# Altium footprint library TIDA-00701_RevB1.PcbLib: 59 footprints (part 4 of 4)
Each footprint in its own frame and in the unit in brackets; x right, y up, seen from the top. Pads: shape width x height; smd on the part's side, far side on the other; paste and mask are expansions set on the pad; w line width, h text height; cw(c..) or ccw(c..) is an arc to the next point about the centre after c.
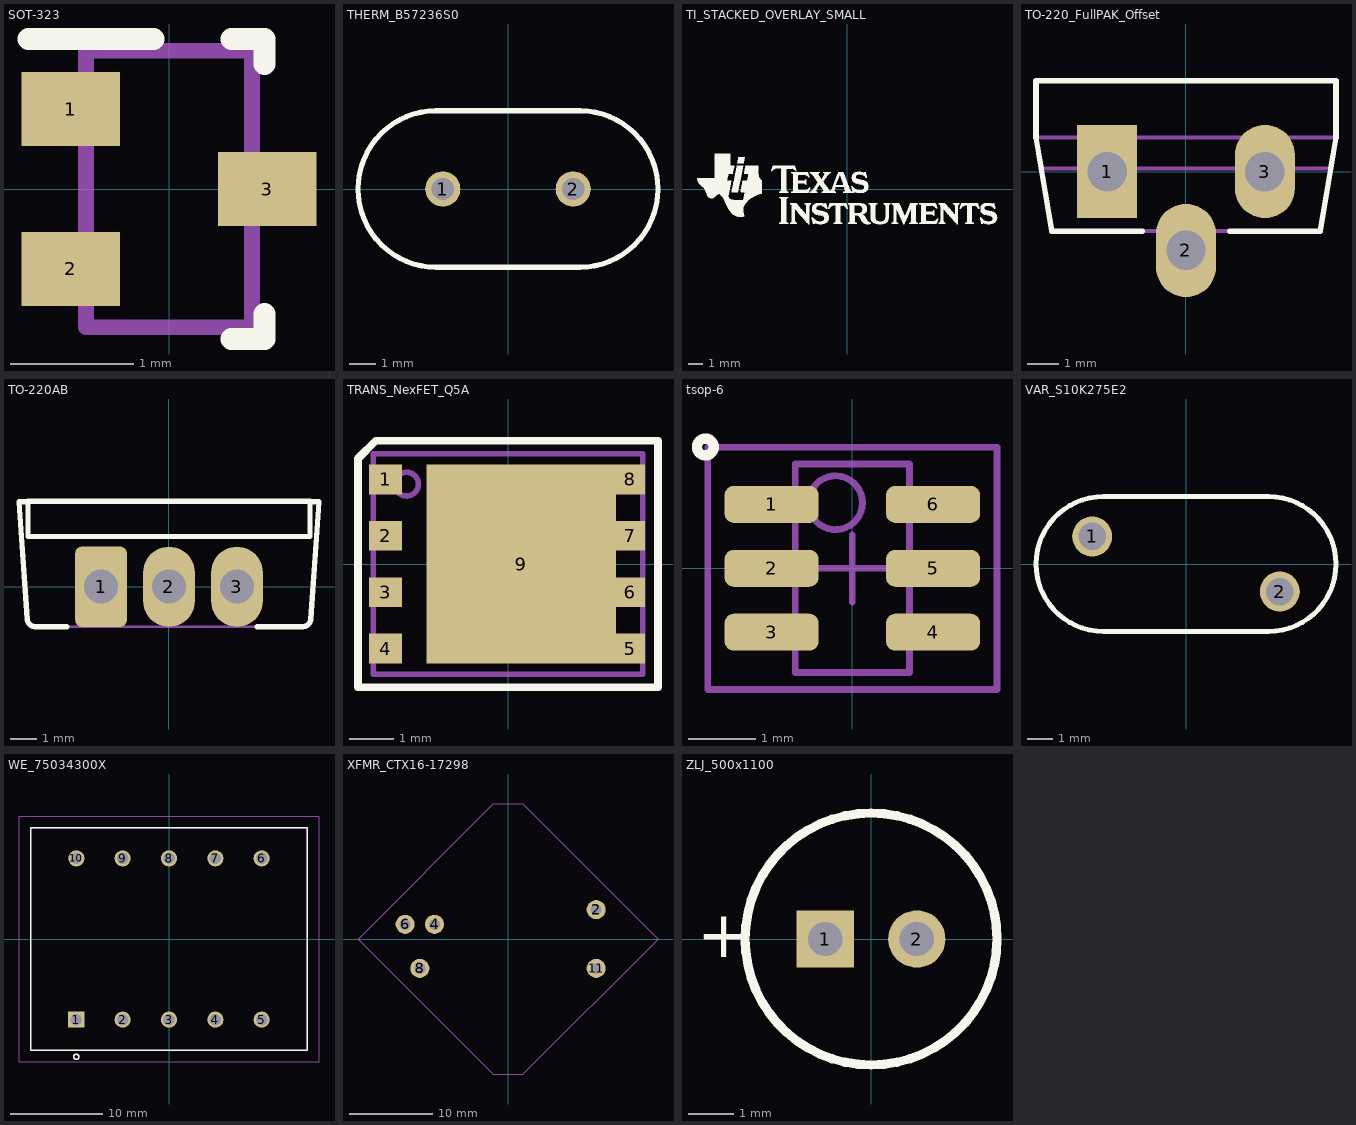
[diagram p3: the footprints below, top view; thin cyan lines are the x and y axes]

## SOT-323 [mm] "Zetex recommended land pattern.  March 2007"
height 1.1
pads (3):
  rect 0.8x0.6 smd: 1(-0.8,0.65) 2(-0.8,-0.65) 3(0.8,0)
Top Overlay:
  lines w0.178: -1.143,1.219 -0.127,1.219 ; 0.508,-1.219 0.775,-1.219 0.775,-1.016 ; 0.508,1.219 0.775,1.219 0.775,1.016
Mechanical 5:
  lines w0.127: -1.125,-0.8 -1.125,-0.5 -0.975,-0.5 -0.935,-0.5 -0.884,-0.5 -0.725,-0.5 -0.675,-0.5 -0.675,-0.8 -0.725,-0.8 -0.884,-0.8 -0.935,-0.8 -0.975,-0.8 -1.125,-0.8 ; -1.125,0.5 -1.125,0.8 -0.975,0.8 -0.935,0.8 -0.884,0.8 -0.725,0.8 -0.675,0.8 -0.675,0.5 -0.725,0.5 -0.884,0.5 -0.935,0.5 -0.975,0.5 -1.125,0.5 ; -0.675,-1.125 -0.675,1.125 0.675,1.125 0.675,-1.125 -0.675,-1.125 ; 0.675,-0.15 0.725,-0.15 0.884,-0.15 0.935,-0.15 0.975,-0.15 1.125,-0.15 1.125,0.15 0.975,0.15 0.935,0.15 0.884,0.15 0.725,0.15 0.675,0.15 0.675,-0.15
  text ".Designator" at 0.434,-0.617 h0.89
3D body: height 1.13, standoff 0.02, extent -1.125,-1.125 1.125,1.125

## THERM_B57236S0 [mm] "EPCOS"
height 16
pads (2):
  round 1.35 hole 0.85: 1(-2.5,0) 2(2.5,0)
Top Overlay:
  lines w0.2: -2.75,-3 cw(c-2.75,0) -2.75,3 2.75,3 cw(c2.75,0) 2.75,-3 -2.75,-3
Mechanical 5:
  lines w0.1: -2.75,-3 cw(c-2.75,0) -2.75,3 2.75,3 cw(c2.75,0) 2.75,-3 -2.75,-3
  text ".Designator" at -1.829,0.686 h0.89
3D body: height 5.5, standoff -2.5, extent -2.797,-0.299 -2.2,0.3
3D body: height 5.5, standoff -2.5, extent 2.202,-0.299 2.8,0.3
3D body: height 15.99, standoff 4.51, extent -5.755,-3 5.7,3

## TI_STACKED_OVERLAY_SMALL [mm]
Top Overlay:
  drawing of 18 lines, arcs and shapes, not listed

## TO-220_FullPAK_Offset [mm] "Infineon  PG-TO220-3-31"
height 19.4
pads (3):
  rect 1.93x3 hole 1.27: 1(-2.54,0)
  oval 1.93x3 hole 1.27: 2(0,-2.54) 3(2.54,0)
Top Overlay:
  lines w0.178: -4.655,0.095 -4.825,1.095 ; -4.325,-1.915 -1.4,-1.915 ; -4.325,-1.915 -4.825,1.085 -4.825,1.095 ; 1.4,-1.915 4.325,-1.915 4.825,1.085 4.825,1.095 ; 4.655,0.095 4.825,1.095 ; -4.825,1.095 -4.825,2.915 4.825,2.915 4.825,1.095
Mechanical 5:
  lines w0.127: -0.89,-1.915 -0.89,-2.058 -0.89,-2.853 0.89,-2.853 0.89,-1.915 ; -4.825,1.095 -4.825,1.085 -4.325,-1.915 4.325,-1.915 4.825,1.085 4.825,1.095 ; -4.825,1.095 -4.825,2.915 4.825,2.915 4.825,1.095 ; -4.825,1.095 4.825,1.095 ; -4.825,1.095 -4.655,0.095 4.655,0.095 4.825,1.095
  text ".Designator" at -0.635,-0.203 h0.89
3D body: height 22.91, standoff -3.95, extent -4.825,-2.845 4.825,2.915

## TO-220AB [mm] "Copied from Altium's version of TO3B"
height 19.4
pads (3):
  rrect25% 1.93x3 hole 1.27: 1(-2.54,0)
  oval 1.93x3 hole 1.27: 2(0,0) 3(2.54,0)
Top Overlay:
  lines w0.2: -5.27,3.175 -5.606,3.175 ; -5.27,3.185 -5.606,3.185 -5.606,3.175 ; -3.81,-1.495 -5,-1.495 cw(c-5,-1.195) -5.297,-1.237 cw(c-5,-1.195) -5.299,-1.216 -5.606,3.175 ; 3.302,-1.495 5,-1.495 ccw(c5,-1.195) 5.297,-1.237 ccw(c5,-1.195) 5.3,-1.216 5.607,3.175 ; 5.27,3.175 5.607,3.175 ; 5.27,3.185 5.607,3.185 5.607,3.175 ; -5.27,1.875 -5.27,3.195 5.27,3.195 5.27,1.875 -5.27,1.875
Mechanical 5:
  lines w0.1: -5.27,3.175 -5.606,3.175 ; -5.27,3.185 -5.606,3.185 -5.606,3.175 ; 5.27,3.175 5.607,3.175 ; 5.27,3.185 5.607,3.185 5.607,3.175 ; -5.606,3.175 -5.299,-1.216 ccw(c-5,-1.195) -5.297,-1.237 ccw(c-5,-1.195) -5,-1.495 5,-1.495 ccw(c5,-1.195) 5.297,-1.237 ccw(c5,-1.195) 5.3,-1.216 5.607,3.175 ; -5.27,1.875 5.27,1.875 5.27,3.195 -5.27,3.195 -5.27,1.875
  text ".Designator" at -0.483,0.61 h0.89
3D body: height 19.42, standoff -3.88, extent -5.606,-1.495 5.607,3.195

## TRANS_NexFET_Q5A [mm] "TI recommended land pattern (nominal) M0139-01"
height 1.1
pads (9):
  rect 0.75x0.675 smd paste-0.1: 1(-2.776,1.917) 2(-2.776,0.639) 3(-2.776,-0.639) 4(-2.776,-1.917)
  rect 0.655x0.675 smd paste-0.1: 5(2.776,-1.917) 6(2.776,-0.639) 7(2.776,0.639) 8(2.776,1.917)
  rect 4.295x4.51 smd paste-2.2: 9(0.301,0)
Top Overlay:
  lines w0.178: -3.4,-2.795 0,-2.795 3.4,-2.795 3.4,0 3.4,2.795 0,2.795 -2.995,2.795 -3.4,2.39 -3.4,0 -3.4,-2.795
Top Paste:
  region: 0.323,0.31 0.323,1.88 1.908,1.88 1.908,0.31
  region: 0.323,-0.31 0.323,-1.88 1.908,-1.88 1.908,-0.31
  region: -1.412,0.31 -1.412,1.88 -0.177,1.88 -0.177,0.31
  region: -1.412,-0.31 -1.412,-1.88 -0.177,-1.88 -0.177,-0.31
Mechanical 5:
  circle w0.127: c-2.3,1.81 r0.269
  lines w0.127: -3.05,-2.5 3.05,-2.5 3.05,2.5 -3.05,2.5 -3.05,-2.5
  text ".Designator" at 0.533,-0.838 h0.89
3D body: height 1.11, standoff 0, extent -3.05,-2.5 3.05,2.5

## tsop-6 [mm] "TSOP, 6-Leads, Body 3.1x1.7mm (max), Pitch 0.95mm, IPC Medium Density"
height 1.1
pads (6):
  rrect50% 1.4x0.55 smd: 1(-1.2,0.95) 2(-1.2,0) 3(-1.2,-0.95) 4(1.2,-0.95) 5(1.2,0) 6(1.2,0.95)
Top Overlay:
  circle w0.152: c-2.184,1.803 r0.125
Mechanical 5:
  text ".Designator" at -0.838,-0.533 h0.89
Mechanical 13:
  circle w0.1: c-0.25,0.975 r0.4
  lines w0.1: -0.85,-1.55 -0.85,1.55 0.85,1.55 0.85,-1.55 -0.85,-1.55
Mechanical 15:
  lines w0.1: -0.5,0 0.5,0 ; 0,-0.5 0,0.5 ; -2.15,-1.8 -2.15,1.8 2.15,1.8 2.15,-1.8 -2.15,-1.8
3D body: height 1.1, standoff 0.1, extent -0.85,-1.55 0.85,1.55
3D body: height 1.1, standoff 1.1, extent -0.657,0.568 0.157,1.382

## VAR_S10K275E2 [mm] "EPCOS"
height 14.5
pads (2):
  round 1.6 hole 1.1: 1(-3.75,1.1) 2(3.75,-1.1)
Top Overlay:
  lines w0.2: -3.3,-2.7 cw(c-3.3,0) -3.3,2.7 3.3,2.7 cw(c3.3,0) 3.3,-2.7 -3.3,-2.7
Mechanical 5:
  lines w0.1: -3.3,-2.7 cw(c-3.3,0) -3.3,2.7 3.3,2.7 cw(c3.3,0) 3.3,-2.7 -3.3,-2.7
  text ".Designator" at -0.203,1.067 h0.89
3D body: height 7, standoff -3, extent -4.172,0.676 -3.325,1.524
3D body: height 7, standoff -3, extent 3.328,-1.524 4.175,-0.676
3D body: height 14.99, standoff 3.01, extent -5.976,-2.7 5.976,2.7

## WE_75034300X [mm] "TRANS OR IND, PITCH 5MM, 29.84X24X33MM, TH-10PIN"
height 33
pads (10):
  rect 1.75x1.75 / inner round 1.75 / far side rect 1.75x1.75 hole 1.25: 1(-10,-8.7)
  round 1.75 hole 1.25: 2(-5,-8.7) 3(0,-8.7) 4(5,-8.7) 5(10,-8.7) 6(10,8.7) 7(5,8.7) 8(0,8.7) 9(-5,8.7) 10(-10,8.7)
Top Overlay:
  circle w0.178: c-10,-12.718 r0.279
  lines w0.178: -14.92,-12 14.92,-12 14.92,12 -14.92,12 -14.92,-12
  text ".Designator" at -15.265,-0.025 h0.89
Mechanical 5:
  circle w0.127: c-10,-8.7 r0.279
  lines w0.127: -14.92,-12 -14.92,12 14.92,12 14.92,-12 -14.92,-12
  text ".Designator" at -1.524,-0.508 h0.89
Mechanical 15:
  lines w0.05: -16.19,-13.27 -16.19,13.27 16.19,13.27 16.19,-13.27 -16.19,-13.27
Mechanical 17:
  text "LEAD LENGTH: 2.54 MM" at -8.948,-5.378 h1
3D body: height 33, standoff 0, extent -14.651,-12.09 15.189,11.91

## XFMR_CTX16-17298 [mil]
pads (5):
  round 90 hole 52: 2(415.78,138.59) 4(-346.48,69.3) 6(-485.08,69.3) 8(-415.78,-138.59) 11(415.78,-138.59)
Mechanical 5:
  lines w5: -707.11,0 -70.71,-636.4 70.71,-636.4 707.11,0 70.71,636.4 -70.71,636.4 -707.11,0
  text ".Designator" at -120.92,-53.03 h40

## ZLJ_500x1100 [mm] "TH, 2-Leads, Dia 5mm,  Lead Spacing 2mm"
height 12.5
pads (2):
  rect 1.25x1.25 hole 0.75: 1(-1,0)
  round 1.25 hole 0.75: 2(1,0)
Top Overlay:
  circle w0.2: c0,0 r2.75
  text "+" at -3.8,-0.4 h1.02
Mechanical 5:
  circle w0.1: c0,0 r2.75
  text "+" at -3.8,-0.4 h0.89
  text ".Designator" at 0.229,-1.245 h0.89
3D body: height 12.51, standoff -3, extent -2.728,-2.745 2.75,2.746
